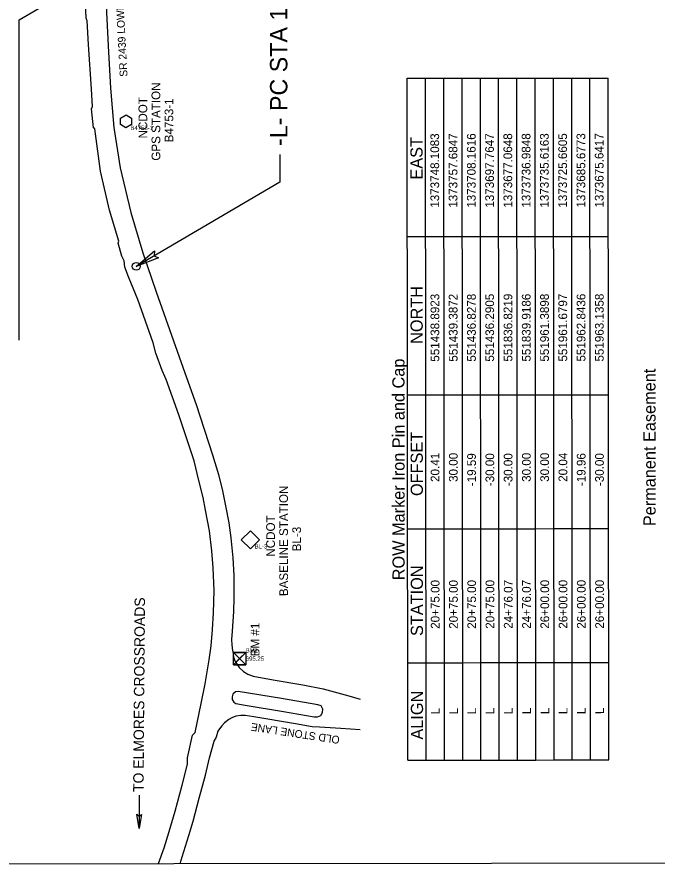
# Model space of a CAD drawing. Extents: x 1373043 to 1375788, y 550128 to 553055.
# Drawn here: x 1373639 to 1374375, y 550417 to 551391 of the extents above; entities that cross this region are included whole.
import ezdxf

# ---------------------------------------------------------------- set-up
doc = ezdxf.new("R2010")
doc.units = 0
for name, color, linetype in [('CTL Bench Mark CELL', 7, 'Continuous'), ('CTL Bench Mark Text', 7, 'Continuous'), ('CTL GPS Vertical CELL', 7, 'Continuous'), ('CTL GPS Vertical Text', 7, 'Continuous'), ('CTL Sheet Border CELL', 7, 'Continuous'), ('CTL Sheet Notes CELL', 7, 'Continuous'), ('CTL Sheet Table Cell', 7, 'Continuous'), ('CTL Sheet Text', 7, 'Continuous'), ('CTL Supplemental Horizontal and Vertical CELL', 7, 'Continuous'), ('CTL Supplemental Horizontal and Vertical Text', 7, 'Continuous'), ('Default', 7, 'Continuous'), ('Exist Roads EOP', 7, 'Continuous'), ('Exist Roads EOP Other', 7, 'Continuous'), ('Prop Horizontal Alignment Station Label', 7, 'Continuous'), ('Prop North Arrow for Plan Sheets CELL', 7, 'Continuous'), ('Prop Terminator CELL', 7, 'Continuous'), ('Scratch_Level_0', 7, 'Continuous')]:
    doc.layers.add(name, color=color, linetype=linetype)

msp = doc.modelspace()

# ---------------------------------------------------------------- linework, layer by layer
at = {"layer": 'CTL Bench Mark CELL'}
msp.add_line((1373894.8, 550652.77), (1373894.8, 550652.77), dxfattribs=at)
msp.add_lwpolyline([(1373887.6, 550659.94), (1373901.97, 550659.94), (1373901.97, 550645.57), (1373887.6, 550645.57)], close=True, dxfattribs=at)
for points in [[(1373901.97, 550659.94), (1373887.6, 550645.57), (1373894.78, 550652.75), (1373901.97, 550645.57), (1373887.6, 550659.94)], [(1373894.78, 550652.75), (1373901.97, 550659.94), (1373887.6, 550659.94), (1373894.78, 550652.75)], [(1373894.78, 550652.75), (1373887.6, 550645.57), (1373901.97, 550645.57), (1373894.78, 550652.75)]]:
    msp.add_lwpolyline(points, dxfattribs=at)
at = {"layer": 'CTL GPS Vertical CELL'}
msp.add_line((1373764.17, 551270.59), (1373764.17, 551270.59), dxfattribs=at)
msp.add_lwpolyline([(1373757.71, 551274.33), (1373764.21, 551277.96), (1373770.71, 551274.38), (1373770.61, 551266.93), (1373764.11, 551263.16), (1373757.71, 551266.78)], close=True, dxfattribs=at)
at = {"layer": 'CTL Sheet Border CELL'}
msp.add_lwpolyline([(1373086.16, 553025.24), (1373088.48, 550416.54), (1374914.56, 550418.17), (1374912.24, 553026.87)], close=True, dxfattribs=at)
at = {"layer": 'CTL Sheet Table Cell'}
for p, q in [((1374087.53, 551320.05), (1374108.53, 551320.07)), ((1374088.22, 550536.05), (1374087.53, 551320.05)), ((1374108.53, 551320.07), (1374129.53, 551320.09)), ((1374109.22, 550536.07), (1374108.53, 551320.07)), ((1374129.53, 551320.09), (1374150.53, 551320.11)), ((1374130.22, 550536.09), (1374129.53, 551320.09)), ((1374150.53, 551320.11), (1374171.53, 551320.13)), ((1374151.22, 550536.11), (1374150.53, 551320.11)), ((1374171.53, 551320.13), (1374192.53, 551320.15)), ((1374172.22, 550536.13), (1374171.53, 551320.13)), ((1374192.53, 551320.15), (1374213.53, 551320.17)), ((1374193.22, 550536.15), (1374192.53, 551320.15)), ((1374213.53, 551320.17), (1374234.53, 551320.18)), ((1374214.22, 550536.17), (1374213.53, 551320.17)), ((1374234.53, 551320.18), (1374255.53, 551320.2)), ((1374235.22, 550536.18), (1374234.53, 551320.18)), ((1374255.53, 551320.2), (1374276.53, 551320.22)), ((1374256.22, 550536.2), (1374255.53, 551320.2)), ((1374276.53, 551320.22), (1374297.53, 551320.24)), ((1374277.22, 550536.22), (1374276.53, 551320.22)), ((1374297.53, 551320.24), (1374318.53, 551320.26)), ((1374298.22, 550536.24), (1374297.53, 551320.24)), ((1374319.22, 550536.26), (1374318.53, 551320.26)), ((1374087.69, 551138.05), (1374108.69, 551138.07)), ((1374108.69, 551138.07), (1374129.69, 551138.09)), ((1374129.69, 551138.09), (1374150.69, 551138.11)), ((1374150.69, 551138.11), (1374171.69, 551138.13)), ((1374171.69, 551138.13), (1374192.69, 551138.15)), ((1374192.69, 551138.15), (1374213.69, 551138.17)), ((1374213.69, 551138.17), (1374234.69, 551138.18)), ((1374234.69, 551138.18), (1374255.69, 551138.2)), ((1374255.69, 551138.2), (1374276.69, 551138.22)), ((1374276.69, 551138.22), (1374297.69, 551138.24)), ((1374297.69, 551138.24), (1374318.69, 551138.26)), ((1374087.85, 550956.05), (1374108.85, 550956.07)), ((1374108.85, 550956.07), (1374129.85, 550956.09)), ((1374129.85, 550956.09), (1374150.85, 550956.11)), ((1374150.85, 550956.11), (1374171.85, 550956.13)), ((1374171.85, 550956.13), (1374192.85, 550956.15)), ((1374192.85, 550956.15), (1374213.85, 550956.17)), ((1374213.85, 550956.17), (1374234.85, 550956.18)), ((1374234.85, 550956.18), (1374255.85, 550956.2)), ((1374255.85, 550956.2), (1374276.85, 550956.22)), ((1374276.85, 550956.22), (1374297.85, 550956.24)), ((1374297.85, 550956.24), (1374318.85, 550956.26)), ((1374087.99, 550802.05), (1374108.99, 550802.07)), ((1374108.99, 550802.07), (1374129.99, 550802.09)), ((1374129.99, 550802.09), (1374150.99, 550802.11)), ((1374150.99, 550802.11), (1374171.99, 550802.13)), ((1374171.99, 550802.13), (1374192.99, 550802.15)), ((1374192.99, 550802.15), (1374213.99, 550802.17)), ((1374213.99, 550802.17), (1374234.99, 550802.18)), ((1374234.99, 550802.18), (1374255.99, 550802.2)), ((1374255.99, 550802.2), (1374276.99, 550802.22)), ((1374276.99, 550802.22), (1374297.99, 550802.24)), ((1374297.99, 550802.24), (1374318.99, 550802.26)), ((1374088.12, 550648.05), (1374109.12, 550648.07)), ((1374109.12, 550648.07), (1374130.12, 550648.09)), ((1374130.12, 550648.09), (1374151.12, 550648.11)), ((1374151.12, 550648.11), (1374172.12, 550648.13)), ((1374172.12, 550648.13), (1374193.12, 550648.15)), ((1374193.12, 550648.15), (1374214.12, 550648.17)), ((1374214.12, 550648.17), (1374235.12, 550648.18)), ((1374235.12, 550648.18), (1374256.12, 550648.2)), ((1374256.12, 550648.2), (1374277.12, 550648.22)), ((1374277.12, 550648.22), (1374298.12, 550648.24)), ((1374298.12, 550648.24), (1374319.12, 550648.26)), ((1374088.22, 550536.05), (1374109.22, 550536.07)), ((1374109.22, 550536.07), (1374130.22, 550536.09)), ((1374130.22, 550536.09), (1374151.22, 550536.11)), ((1374151.22, 550536.11), (1374172.22, 550536.13)), ((1374172.22, 550536.13), (1374193.22, 550536.15)), ((1374193.22, 550536.15), (1374214.22, 550536.17)), ((1374214.22, 550536.17), (1374235.22, 550536.18)), ((1374235.22, 550536.18), (1374256.22, 550536.2)), ((1374256.22, 550536.2), (1374277.22, 550536.22)), ((1374277.22, 550536.22), (1374298.22, 550536.24)), ((1374298.22, 550536.24), (1374319.22, 550536.26))]:
    msp.add_line(p, q, dxfattribs=at)
at = {"layer": 'CTL Supplemental Horizontal and Vertical CELL'}
msp.add_line((1373907.11, 550789.34), (1373907.11, 550789.34), dxfattribs=at)
msp.add_lwpolyline([(1373896.68, 550789.38), (1373907.17, 550799.86), (1373917.67, 550789.36), (1373907.18, 550778.87)], close=True, dxfattribs=at)
at = {"layer": 'Default'}
msp.add_line((1373779.37, 550495.71), (1373779.46, 550457.5), dxfattribs=at)
at = {"layer": 'Exist Roads EOP'}
for points in [[(1373734.95, 551213.33), (1373728.45, 551261.74), (1373727.03, 551263.26), (1373724.74, 551285.08), (1373725.63, 551287.71), (1373724.36, 551307.73), (1373721.1, 551358.8), (1373719.46, 551386.07), (1373718.5, 551389.08), (1373718.04, 551398.12), (1373718.06, 551403.77), (1373716.16, 551450.55), (1373713.5, 551495.48), (1373710.98, 551534.9), (1373710, 551540.42), (1373708.89, 551563.59), (1373708.4, 551585.86), (1373707.23, 551630.94), (1373703.95, 551671.57)], [(1373727.18, 551672.91), (1373729, 551632.12), (1373731.99, 551597.22), (1373731.56, 551586.11), (1373735.22, 551557.03), (1373736.28, 551535.01), (1373735.28, 551516.66), (1373735.7, 551497.28), (1373738.71, 551451.68), (1373741.31, 551403.72), (1373743.8, 551357.51), (1373746.37, 551308.82), (1373750.32, 551263.43), (1373757.44, 551216.95), (1373769.77, 551165.72), (1373783.47, 551119.33), (1373798.77, 551074.42), (1373816.56, 551024.76), (1373831.9, 550981.28), (1373844.68, 550944.87), (1373863.48, 550887.05)], [(1373842.39, 550880.17), (1373824.84, 550932.94), (1373810.49, 550973.55), (1373805.66, 550984.08), (1373798.51, 551004.13), (1373795.34, 551015.91), (1373777.85, 551065.75), (1373766.92, 551091.65), (1373762.8, 551102.71), (1373762.13, 551110), (1373759.49, 551115.59), (1373755.32, 551130.29), (1373755.89, 551132.73), (1373745.34, 551168.38), (1373734.95, 551213.33)], [(1373801.6, 550417.18), (1373807.95, 550435.34), (1373813.84, 550454.05), (1373820.74, 550477.46), (1373828.79, 550507.17), (1373834.87, 550531.48), (1373835.08, 550538.69), (1373840.7, 550564.64), (1373843.66, 550567.86), (1373850.72, 550601.01), (1373855.38, 550623.88), (1373859.82, 550651.49), (1373862.11, 550667.48), (1373863.53, 550686.22), (1373864.76, 550705.35), (1373865.51, 550731.15), (1373864.5, 550757.06), (1373863.03, 550776.51), (1373860.11, 550799.56), (1373855.74, 550823.54), (1373852.89, 550837.87), (1373848.02, 550857.46), (1373842.39, 550880.17)], [(1373863.48, 550887.05), (1373870.4, 550864.47), (1373875.14, 550845.87), (1373878.72, 550828.39), (1373882.43, 550808.78), (1373884.89, 550791.53), (1373886.94, 550768.68), (1373888.15, 550748.24), (1373888.27, 550722.52), (1373887.92, 550707.02), (1373886.3, 550684.21), (1373885.59, 550674.76), (1373885.74, 550668.48), (1373886.44, 550661.78)], [(1373826.47, 550417.2), (1373828.94, 550424.77), (1373836.47, 550449.45), (1373841.38, 550465.78), (1373848.47, 550492.36), (1373855.55, 550518.88), (1373860.26, 550538.51), (1373865.47, 550557.99), (1373868.12, 550562.55)]]:
    msp.add_lwpolyline(points, dxfattribs=at)
at = {"layer": 'Exist Roads EOP Other'}
for points in [[(1373886.86, 550661.25), (1373887.77, 550654.49), (1373889.82, 550649.35), (1373894.16, 550642.69), (1373899.2, 550637.9), (1373904.44, 550634.7), (1373910.22, 550632.45), (1373933.5, 550628.21), (1373967.64, 550622.7), (1373990.79, 550618.2), (1374020.22, 550609.82), (1374033.51, 550606.11)], [(1373942.76, 550606.82), (1373892.96, 550615.08), (1373889.99, 550614.68), (1373887.17, 550611.91), (1373886.16, 550608.7), (1373886.28, 550605.71), (1373888.18, 550602.82), (1373890.59, 550601.29), (1373901.3, 550599.12), (1373945.21, 550592.13), (1373980.57, 550585.99), (1373984.2, 550585.73), (1373988.06, 550587.18), (1373990.06, 550590.74), (1373990.56, 550594.83), (1373988.41, 550598.33), (1373984.68, 550599.73), (1373942.76, 550606.82)], [(1374033.54, 550570.91), (1374011.1, 550572.31), (1373986.75, 550573.76), (1373978.19, 550574.51), (1373959.11, 550577.68), (1373911, 550585.92), (1373901.08, 550587.48), (1373896.32, 550587.49), (1373890.48, 550586.47), (1373885.85, 550584.63), (1373882.25, 550582.63), (1373877.3, 550578.77), (1373874.2, 550575.45), (1373871.86, 550572.08), (1373869.94, 550569.19), (1373867.68, 550562.61)]]:
    msp.add_lwpolyline(points, dxfattribs=at)
at = {"layer": 'Prop Horizontal Alignment Station Label'}
for p, q in [((1373641.24, 551387.24), (1373727.72, 551437.84)), ((1373641.56, 551018.81), (1373641.24, 551387.24))]:
    msp.add_line(p, q, dxfattribs=at)
msp.add_lwpolyline([(1373941.14, 551232.31), (1373941.17, 551200.45), (1373775.97, 551103.81)], dxfattribs=at)
msp.add_circle((1373775.97, 551103.81), 4.5, dxfattribs=at)
at = {"layer": 'Prop North Arrow for Plan Sheets CELL'}
msp.add_lwpolyline([(1373782.21, 550473.7), (1373779.46, 550457.5), (1373776.54, 550473.78), (1373779.43, 550471.72)], close=True, dxfattribs=at)
at = {"layer": 'Prop Terminator CELL'}
msp.add_lwpolyline([(1373801.62, 551113.43), (1373775.97, 551103.81), (1373796.98, 551121.66), (1373796.43, 551115.77)], close=True, dxfattribs=at)

# ---------------------------------------------------------------- texts
at = {"layer": 'CTL Bench Mark Text'}
msp.add_text('BM #1', height=10, rotation=90.05097, dxfattribs=at).set_placement((1373917.66, 550655.49))
at = {"layer": 'CTL GPS Vertical Text'}
for s, p in [('GPS STATION', (1373803.64, 551225.33)), ('NCDOT', (1373788.62, 551250.9)), ('B4753-1', (1373818.62, 551246.44))]:
    msp.add_text(s, height=10, rotation=90.05097, dxfattribs=at).set_placement(p)
at = {"layer": 'CTL Sheet Notes CELL'}
for s, p in [('EAST', (1374105.13, 551203.6)), ('NORTH', (1374105.3, 551014.66)), ('ROW Marker Iron Pin and Cap', (1374084.54, 550742.85)), ('Permanent Easement', (1374373.02, 550805.08)), ('OFFSET', (1374105.45, 550839.71)), ('STATION', (1374105.6, 550678.77)), ('ALIGN', (1374105.7, 550559.66))]:
    msp.add_text(s, height=14, rotation=90.05095, dxfattribs=at).set_placement(p)
at = {"layer": 'CTL Sheet Text'}
for s, p in [('1373748.1083', (1374124.16, 551171.21)), ('1373757.6847', (1374145.16, 551171.23)), ('1373708.1616', (1374166.16, 551171.25)), ('1373697.7647', (1374187.16, 551171.27)), ('1373677.0648', (1374208.16, 551171.29)), ('1373736.9848', (1374229.16, 551171.3)), ('1373735.6163', (1374250.16, 551171.32)), ('1373725.6605', (1374271.16, 551171.34)), ('1373685.6773', (1374292.16, 551171.36)), ('1373675.6417', (1374313.16, 551171.38)), ('551438.8923', (1374124.32, 550994.17)), ('551439.3872', (1374145.32, 550994.19)), ('551436.8278', (1374166.32, 550994.21)), ('551436.2905', (1374187.32, 550994.23)), ('551836.8219', (1374208.32, 550994.25)), ('551839.9186', (1374229.32, 550994.27)), ('551961.3898', (1374250.32, 550994.28)), ('551961.6797', (1374271.32, 550994.3)), ('551962.8436', (1374292.32, 550994.32)), ('551963.1358', (1374313.32, 550994.34)), ('20.41', (1374124.44, 550855.94)), ('30.00', (1374145.44, 550855.95)), ('-19.59', (1374166.44, 550851.01)), ('-30.00', (1374187.44, 550851.03)), ('-30.00', (1374208.44, 550851.05)), ('30.00', (1374229.44, 550856.03)), ('30.00', (1374250.44, 550856.05)), ('20.04', (1374271.44, 550856.07)), ('-19.96', (1374292.44, 550851.12)), ('-30.00', (1374313.44, 550851.14)), ('20+75.00', (1374124.59, 550687.05)), ('20+75.00', (1374145.59, 550687.07)), ('20+75.00', (1374166.59, 550687.09)), ('20+75.00', (1374187.59, 550687.11)), ('24+76.07', (1374208.59, 550687.13)), ('24+76.07', (1374229.59, 550687.15)), ('26+00.00', (1374250.59, 550687.17)), ('26+00.00', (1374271.59, 550687.19)), ('26+00.00', (1374292.59, 550687.2)), ('26+00.00', (1374313.59, 550687.22)), ('L', (1374124.68, 550588.78)), ('L', (1374145.68, 550588.8)), ('L', (1374166.68, 550588.82)), ('L', (1374187.68, 550588.83)), ('L', (1374208.68, 550588.85)), ('L', (1374229.68, 550588.87)), ('L', (1374250.68, 550588.89)), ('L', (1374271.68, 550588.91)), ('L', (1374292.68, 550588.93)), ('L', (1374313.68, 550588.95))]:
    msp.add_text(s, height=10, rotation=90.05095, dxfattribs=at).set_placement(p)
at = {"layer": 'CTL Supplemental Horizontal and Vertical Text'}
for s, p in [('BASELINE STATION', (1373950.46, 550724.63)), ('NCDOT', (1373935.42, 550769.97)), ('BL-3', (1373965.41, 550776.13))]:
    msp.add_text(s, height=10, rotation=90.05097, dxfattribs=at).set_placement(p)
at = {"layer": 'Default'}
for s, height, rotation, p in [('SR 2439 LOWELL BETHESDA ROAD  ', 8.8889, 93.03968, (1373765.95, 551322)), ('TO ELMORES CROSSROADS', 12, 89.56371, (1373784.41, 550499.35)), ('OLD STONE LANE', 8.8889, 171.36797, (1374010.33, 550563.38))]:
    msp.add_text(s, height=height, rotation=rotation, dxfattribs=at).set_placement(p)
at = {"layer": 'Prop Horizontal Alignment Station Label'}
msp.add_text('-L- PC STA 17+35.92', height=20, rotation=90.05095, dxfattribs=at).set_placement((1373949.79, 551242.25))
at = {"layer": 'Scratch_Level_0'}
for s, p in [('B4753-1', (1373769.24, 551260.58)), ('BL-3', (1373912.11, 550779.34)), ('BM1', (1373901.8, 550659.77)), ('695.25', (1373901.8, 550650.27))]:
    msp.add_text(s, height=5, dxfattribs=at).set_placement(p)

doc.saveas('drawing.dxf')
